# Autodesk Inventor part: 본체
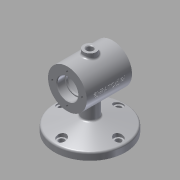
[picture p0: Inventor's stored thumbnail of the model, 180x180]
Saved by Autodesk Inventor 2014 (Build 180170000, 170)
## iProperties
Created: 2018-12
Part Number: 본체
Material: Aluminum 6061
Document SubType Name: Modeling
Designer: kh
Density: 2.71 g/cm^3
Appearance: Aluminum - Flat
Mass: 687.366 g
Surface Area: 556.043 cm^2
Volume: 253.641 cm^3
Author: kh
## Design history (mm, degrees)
sketch "Sketch1"
  geometry: C1 r 55 at (0, 0); 1 further point
  constraints: 1 centre point, 1 coincident
  dimensions: "d0" = 110 diameter of C1
extrude "Extrusion1" new body sketch "Sketch1" distance "d1" = 11; taper "d2" = 0 deg
sketch "Sketch2"
  geometry: L1 (0, 0)-(0, 75); L2 (-55, 0)-(55, 0) reference; C1 r 30 at (0, 75)
  constraints: 2 end point, 1 centre point, 1 vertical
  dimensions: "d3" = 60 diameter of C1; "d4" = 75 distance from line of L1.end L2
extrude "Extrusion2" join sketch "Sketch2" stored distance "d5" = 70; taper "d6" = 0 deg
sketch "Sketch3"
  geometry: C1 r 30 at (0, 0) reference; C2 r 16 at (0, 0); 1 further point
  constraints: 1 centre point, 1 coincident
  dimensions: "d7" = 32 diameter of C2
extrude "Extrusion3" cut sketch "Sketch3" distance "d8" = 12; taper "d9" = 0 deg
sketch "Sketch4"
  geometry: C1 r 16 at (0, 0) reference; C2 r 14 at (0, 0); 1 further point
  constraints: 1 centre point, 1 coincident
  dimensions: "d10" = 28 diameter of C2
extrude "Extrusion4" cut sketch "Sketch4" distance "d11" = 3; taper "d12" = 0 deg
sketch "Sketch6"
  geometry: C1 r 30 at (0, 75) reference; C2 r 25 at (0, 75); 1 further point
  constraints: 1 centre point, 1 coincident
  dimensions: "d13" = 50 diameter of C2
extrude "Extrusion5" cut sketch "Sketch6" stored distance "d14" = 40; taper "d15" = 0 deg
sketch "Sketch7"
  geometry: C1 r 30 at (0, 0) reference; C2 r 16 at (0, 0); 1 further point
  constraints: 1 centre point, 1 coincident
  dimensions: "d16" = 32 diameter of C2
extrude "Extrusion6" cut sketch "Sketch7" distance "d17" = 12; taper "d18" = 0 deg
sketch "Sketch8"
  geometry: C1 r 16 at (0, 0) reference; C2 r 14 at (0, 0); 1 further point
  constraints: 1 centre point, 1 coincident
  dimensions: "d19" = 28 diameter of C2
extrude "Extrusion7" cut sketch "Sketch8" distance "d20" = 3; taper "d21" = 0 deg
sketch "Sketch9"
  geometry: L1 (0, 23)-(0, -23); L2 (-23, 0)-(23, 0); C1 r 30 at (0, 0) reference; A1 r 23 centre (0, 0) between (0, 23) and (0, -23); 6 further points
  constraints: 5 coincident, 4 end point, 4 point on circle, 2 midpoint, 1 centre point, 1 perpendicular, 1 vertical
  dimensions: "d22" = 46 diameter of A1
hole "Hole1" sketch "Sketch9" at (0, 23), (23, 0), (0, -23), (-23, 0) diameter "d23" = 3.459; stored, may be unused: countersink angle "d27" = 90 deg, drill point angle "d29" = 118 deg; dims "d24" = 8, "d25" = 4, "d26" = 2, "d28" = 10
mirror "Mirror1"
sketch "Sketch10"
  geometry: C1 r 55 at (0, 0) reference; C2 r 12 at (0, 0); 1 further point
  constraints: 1 centre point, 1 coincident
  dimensions: "d30" = 24 diameter of C2
extrude "Extrusion8" join sketch "Sketch10" stored distance "d31" = 3; taper "d32" = 0 deg
workplane "Work Plane1"
sketch "Sketch11"
  geometry: C1 r 55 at (0, 0) reference; C2 r 10 at (0, 0); 1 further point
  constraints: 1 centre point, 1 coincident
  dimensions: "d34" = 20 diameter of C2
extrude "Extrusion9" join sketch "Sketch11" stored distance "d35" = 3; taper "d36" = 0 deg
sketch "Sketch12"
  geometry: C1 r 10 at (0, 0) reference; C2 r 5 at (0, 0); 1 further point
  constraints: 1 centre point, 1 coincident
  dimensions: "d37" = 10 diameter of C2
extrude "Extrusion10" cut sketch "Sketch12" stored distance "d38" = 3; taper "d39" = 0 deg
chamfer "Chamfer1" distance "d40" = 1; stored, may be unused: second distance "d41" = 2, angle "d42" = 45 deg
sketch "Sketch14"
  geometry: L1 (55, 11)-(-55, 11) reference; L2 (55, 0)-(55, 11) reference; L3 (0, 0)-(0, 22.157); L4 (12, 11)-(12, 45) reference; L5 (55, 11)-(12, 22.522); L6 (12, 11)-(12, 22.522); L7 (12, 11)-(55, 11)
  constraints: 8 end point, 2 collinear, 1 parallel, 1 point on line
  dimensions: "d43" = 75 deg angle of L5 L2
revolve "Revolution1" sketch "Sketch14" stored, may be unused: angle "d44" = 90 deg
workplane "Work Plane2"
sketch "Sketch15"
  geometry: L1 (-24.887, 85.448)-(24.887, 85.448); L2 (24.887, 85.448)-(24.887, 64.552); L3 (24.887, 64.552)-(-24.887, 64.552); L4 (-24.887, 64.552)-(-24.887, 85.448); L5 (-24.887, 75)-(24.887, 75); L6 (0, 64.552)-(0, 85.448); L7 (-35, 105)-(-35, 45) reference; 1 further point
  constraints: 4 end point, 4 midpoint, 2 other
  dimensions: "d46" = 35 distance from line of L6.end L7; "d47" = 30 vertical distance of L5.start L7.start
emboss "Emboss1" sketch "Sketch15" dims "d1" = 11, "d2" = 0, "d48" = 0.5, "d49" = 0
fillet "Fillet1" dims "d50" = 3
chamfer "Chamfer2" distance "d51" = 1; stored, may be unused: second distance "d52" = 2, angle "d53" = 45 deg
fillet "Fillet2" dims "d54" = 0.3
fillet "Fillet3" dims "d55" = 3
sketch "Sketch17"
  geometry: L1 (0, 44)-(0, -44); L2 (-44, 0)-(44, 0); C1 r 55 at (0, 0) reference; C2 r 4.5 at (0, 44); C3 r 4.5 at (-44, 0); C4 r 4.5 at (44, 0); C5 r 4.5 at (0, -44); A1 r 44 centre (0, 0) between (0, 44) and (0, -44); 2 further points
  constraints: 5 centre point, 5 coincident, 4 end point, 4 point on circle, 2 midpoint, 1 perpendicular, 1 vertical
  dimensions: "d58" = 88 diameter of A1; "d59" = 9 diameter of C2; "d60" = 9 diameter of C3; "d61" = 9 diameter of C4; "d62" = 9 diameter of C5
extrude "Extrusion11" cut sketch "Sketch17" distance "d63" = 10; taper "d64" = 0 deg
sketch "Sketch18" dims "d11" = 3
  geometry: C1 r 4.5 at (0, 0) reference; C2 r 7 at (0, 0); 1 further point
  constraints: 1 centre point, 1 coincident
  dimensions: "d66" = 14 diameter of C2
extrude "Extrusion12" cut sketch "Sketch18" stored distance "d67" = 10; taper "d68" = 0 deg
pattern_circular "Circular Pattern1" dims angle "d70" = 360 deg
body "Solid1"
other parameters: "d33" = 112
